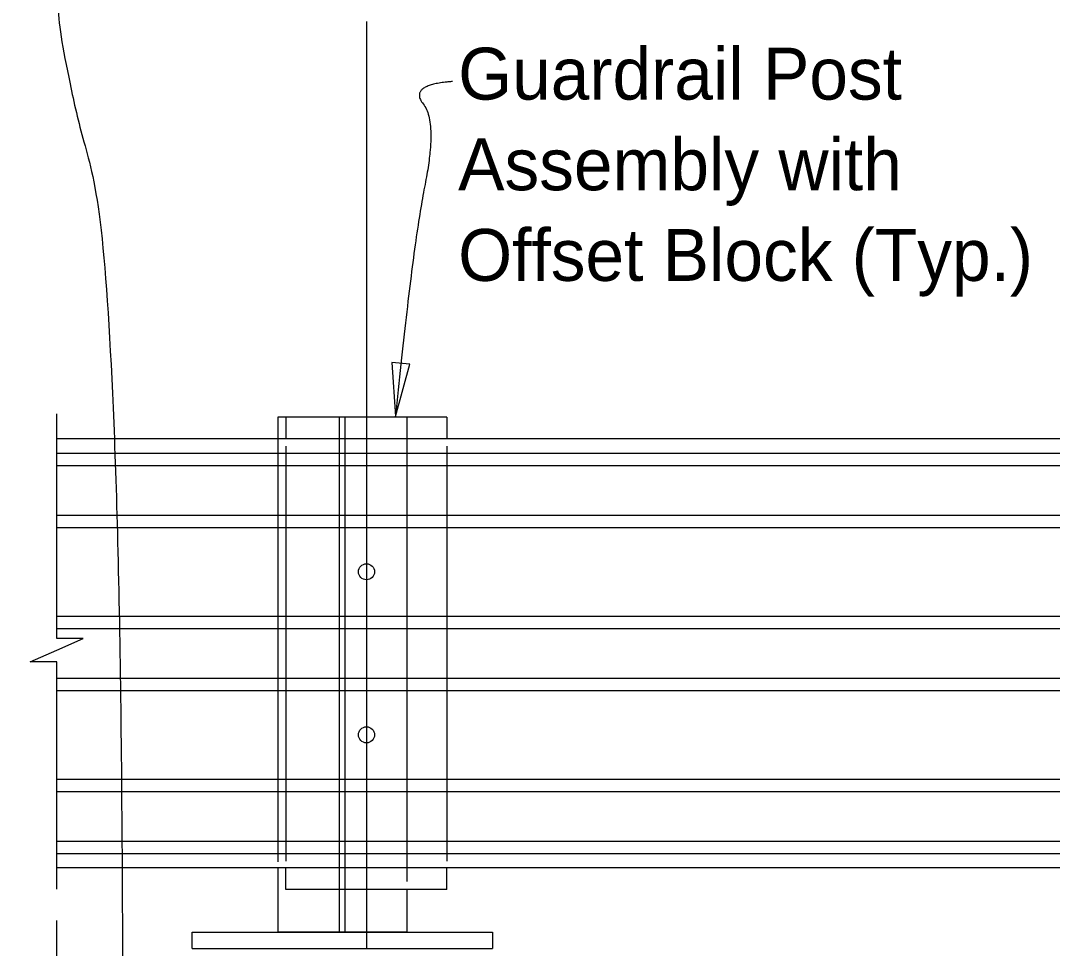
# Model space of a CAD drawing. Extents: x 21526.6 to 21595.9, y 56114.9 to 56157.2.
# Drawn here: x 21527.103 to 21531.109, y 56135.21 to 56138.813 of the extents above; entities that cross this region are included whole.
import ezdxf

# ---------------------------------------------------------------- set-up
doc = ezdxf.new("R2010")
doc.units = 0
for name, color, linetype in [('Patterning', 7, 'Continuous'), ('PlotBorder_dp', 7, 'Continuous'), ('SheetBorder_dp', 7, 'Continuous'), ('TextMisc', 7, 'Continuous')]:
    doc.layers.add(name, color=color, linetype=linetype)

msp = doc.modelspace()

# ---------------------------------------------------------------- linework, layer by layer
at = {"layer": 'Patterning'}
for p, q in [((21528.4455, 56138.8093), (21528.4455, 56135.2123)), ((21528.758, 56137.2726), (21528.133, 56137.2726)), ((21528.133, 56137.2726), (21528.133, 56137.1892)), ((21528.758, 56137.2726), (21528.758, 56137.1892)), ((21528.133, 56137.1607), (21528.133, 56135.5488)), ((21528.758, 56137.1607), (21528.758, 56135.5488)), ((21528.133, 56135.4392), (21528.133, 56135.5226)), ((21528.758, 56135.4392), (21528.758, 56135.5226)), ((21528.758, 56135.4392), (21528.133, 56135.4392))]:
    msp.add_line(p, q, dxfattribs=at)
at = {"layer": 'PlotBorder_dp'}
msp.add_lwpolyline([(21528.5583, 56137.2748), (21528.614, 56137.4786), (21528.5438, 56137.4856)], close=True, dxfattribs=at)
for points in [[(21527.2427, 56135.4395), (21527.2427, 56136.3228), (21527.1393, 56136.3228), (21527.2427, 56136.3678), (21527.346, 56136.4128), (21527.2427, 56136.4128), (21527.2427, 56137.2857)], [(21527.2427, 56134.3351), (21527.2427, 56134.9021), (21527.1393, 56134.9021), (21527.2427, 56134.9471), (21527.346, 56134.9921), (21527.2427, 56134.9921), (21527.2427, 56135.3182)]]:
    msp.add_lwpolyline(points, dxfattribs=at)
for points in [[(21527.3644, 56139.6956), (21527.0208, 56139.6041), (21527.2362, 56139.0828), (21527.253, 56138.6974), (21527.5005, 56137.7639), (21527.5005, 56134.6471)], [(21528.779, 56138.5761), (21528.6077, 56138.5632), (21528.7217, 56138.419), (21528.6236, 56137.9315), (21528.5583, 56137.2748)]]:
    msp.add_open_spline(points, degree=2, dxfattribs=at)
at = {"layer": 'SheetBorder_dp'}
for p, q in [((21528.1017, 56137.2726), (21528.1017, 56135.5456)), ((21528.3413, 56135.2726), (21528.3413, 56137.2726)), ((21528.3622, 56135.2726), (21528.3622, 56137.2726)), ((21528.6017, 56137.2726), (21528.6017, 56135.4691))]:
    msp.add_line(p, q, dxfattribs=at)
at = {"layer": 'TextMisc'}
for p, q in [((21528.6017, 56137.2726), (21528.1017, 56137.2726)), ((21534.2788, 56137.1892), (21527.2426, 56137.1892)), ((21527.2426, 56137.1336), (21534.2788, 56137.1336)), ((21527.2426, 56137.0854), (21534.2788, 56137.0854)), ((21527.2426, 56136.8926), (21534.2788, 56136.8926)), ((21527.2426, 56136.8444), (21534.2788, 56136.8444)), ((21527.2426, 56136.5004), (21534.2788, 56136.5004)), ((21527.2426, 56136.4522), (21534.2788, 56136.4522)), ((21527.2426, 56136.2594), (21534.2788, 56136.2594)), ((21527.2426, 56136.2112), (21534.2788, 56136.2112)), ((21527.2426, 56135.8673), (21534.2788, 56135.8673)), ((21527.2426, 56135.8191), (21534.2788, 56135.8191)), ((21527.2426, 56135.6262), (21534.2788, 56135.6262)), ((21527.2426, 56135.578), (21534.2788, 56135.578)), ((21534.2788, 56135.5225), (21527.2426, 56135.5225)), ((21528.1017, 56135.5225), (21528.1017, 56135.2726)), ((21528.6017, 56135.4392), (21528.6017, 56135.2726)), ((21527.7684, 56135.2726), (21528.9351, 56135.2726)), ((21527.7684, 56135.2101), (21527.7684, 56135.2726)), ((21528.6017, 56135.2726), (21528.1017, 56135.2726)), ((21528.9351, 56135.2726), (21528.9351, 56135.2101)), ((21527.7684, 56135.2101), (21528.9351, 56135.2101))]:
    msp.add_line(p, q, dxfattribs=at)
for centre in [(21528.4455, 56136.6725), (21528.4455, 56136.0393)]:
    msp.add_circle(centre, 0.0312, dxfattribs=at)

# ---------------------------------------------------------------- texts
at = {"layer": 'PlotBorder_dp'}
for s, p in [('Guardrail Post ', (21528.8015, 56138.506)), ('Assembly with ', (21528.8015, 56138.154)), ('Offset Block (Typ.)', (21528.8015, 56137.802))]:
    msp.add_text(s, height=0.2016, dxfattribs=at).set_placement(p)

doc.saveas('drawing.dxf')
